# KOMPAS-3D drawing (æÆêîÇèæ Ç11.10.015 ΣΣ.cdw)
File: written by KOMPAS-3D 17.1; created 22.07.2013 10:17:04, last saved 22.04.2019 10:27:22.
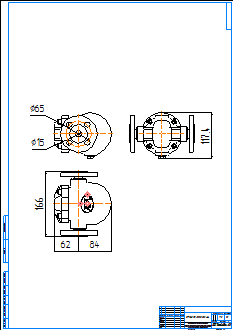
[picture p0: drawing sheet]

Sheet 1: A1, portrait

Title block, sheet 1: name: СТИМАКС А11.10.015 фф; material: Внимание! Данный продукт является объектом авторского права ООО «Торговый Дом АДЛ». / Запрещается изменение, копирование, распространение / (в том числе путем копирования на другие сайты и ресурсы в Интернете) / или любое иное использование информации и объектов без предварительного / согласия правообладателя (ООО «Торговый Дом АДЛ»).; mass: 7,5; sheets: 1; organisation: ООО "Торговый дом АДЛ"; sheet format: A1; stored path: \\adlc.lan\data\АДЛ_ПКД\3D-модели\ADL production\Конденсатоотводчики СТИМАКС\Поплавковые\Серия А11\KOMPAS 2D\СТИМАКС А11.10.015 фф.cdw

Views: Вид 1, Проекционный вид 2
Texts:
  Klimkovich
  ADL
Dimensions and other numbers on the sheet: 15; 166; 62; 84; 1:1; 1; 7,5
